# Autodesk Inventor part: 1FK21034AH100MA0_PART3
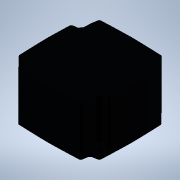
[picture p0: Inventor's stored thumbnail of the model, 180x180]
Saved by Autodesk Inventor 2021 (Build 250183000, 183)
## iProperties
Created: 2025-04
Part Number: 1FK21034AH100MA0_PART3
Material: Generic
Catalog Web Link: www.3dfindit.com
Description: -Servo synchronous motor
Document SubType Name: Modeling
Designer: psAdmin
Mass: 116.584 g
Surface Area: 147.122 cm^2
Volume: 116.584 cm^3
Density: 1 g/cm^3
Appearance: PSOLRGB-38-46-56
Category: PARTsolutions
Title: 1FK21034AH100MA0_PART3
Author: Cadenas PARTsolutions
Comments: Servo synchronous motor
Sending System: PARTsolutions
Preprocessor: ST-DEVELOPER v19.3
PSOL_IDENT_0: {$CADENAS_DATA/23d-libs/siemens_ag/_cat_/39/97/1fk21034ah100ma0.prj},213 {VTYP=3D},{NB=1FK21034AH100
PSOL_IDENT_1: MA0_PART3},{LINA=1FK21034AH100MA0_PART3},{NN=1FK21034AH100MA0_PART3},{NOPRJ=TRUE},{DATE=19.08.2025 1
PSOL_IDENT_2: 4:00:33},{GEOMDATE=30.07.2025 02:02:21},{VERSION=},{LINEID=10},{WBVAR=},{WBNUMERIC=}  {NB=1FK21034AH
PSOL_IDENT_3: 100MA0_PART3},{LINA=1FK21034AH100MA0_PART3},{KT=DUMMY},{PREVIEW=../../../_pool_/d3/78/p_d211_xx_0093
PSOL_IDENT_4: 4j.png},{DESCSHORT=SIMOTICS S-1FK2 HD, SINAMICS S210 3AC 400V-480V, 1.01 Nm, 4500 rpm},{DESCLONG=SIM
PSOL_IDENT_5: OTICS S-1FK2 HD servo motor M0=1.27 Nm; PN = 0.48 kW at nN=4500 rpm (380-480 V); PN = 0.3 kW at nN=2
PSOL_IDENT_6: 500 rpm (200-240 V); with holding brake; degree of protection IP64; cylindrical shaft D14 x 30 mm; a
PSOL_IDENT_7: bsolute encoder 22-bit + 12-bit multiturn (encoder AM22DQC); with OCC interface; plug size M17, rota
PSOL_IDENT_8: table; SIMOTICS S-1FK2 servomotorfor a wide range of uses in industrial environments. SIMOTICS S‑1FK
PSOL_IDENT_9: 2 servomotors are compact synchronous motors with a high dynamic performance that set themselves apa
PSOL_IDENT_10: rt as a result of their high power density, degree of protection and overload capability. The motors
PSOL_IDENT_11: are available in two variants: as High Dynamic variant (highest dynamic performance as a result of
PSOL_IDENT_12: the low intrinsic moment of inertia for applications demanding a high dynamic performance with low m
PSOL_IDENT_13: oved masses) - and as Compact variant (precise and stable closed-loop control for medium up to large
PSOL_IDENT_14: moved masses as a result of a medium intrinsic moment of inertia). SIMOTICSS‑1FK2 servomotors fully
PSOL_IDENT_15: exploit their strengths in a system with the SINAMICSS210 frequency converter and simple connection
PSOL_IDENT_16: using the one cable connection (OCC). Advantages include the short control and positioning times, f
PSOL_IDENT_17: ast and precise correction of disturbing quantities as well as stable control with a high dynamic pe
PSOL_IDENT_18: rformance. The servo motors can be configured to address a wide range of requirements. For example w
PSOL_IDENT_19: ith and without holding brake, IP64 or IP65 degree of protection, singleturn or multiturn absolute e
PSOL_IDENT_20: ncoders - to name just a few. Further, the servomotors are available in different shaft heights exte
PSOL_IDENT_21: nding from 20 to 100. A shaft sealing ring is available to achieve an IP65 degree of protection and
PSOL_IDENT_22: for subsequent mounting at the motor or as spare part. SIMOTICS - the optimum motor for each and eve
PSOL_IDENT_23: ry motion control application.},{INTNO=195125454019},{SUPPLIERALTNO=1FK2103-4AH10-0MA0},{MANUID=1FK2
PSOL_IDENT_24: 1034AH100MA0},{MANUNAME=Siemens},{MANUTYPEDESC=SYNCHRONOUS MOTOR 1FK2 HD 1,27 NM},{AAU732=SIMOTICS},
PSOL_IDENT_25: {AAO057=S-1FK2},{AAU734=SIMOTICS S-1FK2 HD servo motor M0=1.27 Nm; PN = 0.48 kW at nN=4500 rpm (380-
PSOL_IDENT_26: 480 V); PN = 0.3 kW at nN=2500 rpm (200-240 V); with holding brake; degree of protection IP64; cylin
PSOL_IDENT_27: drical shaft D14 x 30 mm; absolute encoder 22-bit + 12-bit multiturn (encoder AM22DQC); with OCC int
PSOL_IDENT_28: erface; plug size M17, rotatable;},{AAW338=SYNCHRONOUS MOTOR 1FK2 HD 1,27 NM},{AAO742=SIMOTICS},{AAO
PSOL_IDENT_29: 663=4034106444921},{NOCUPEROU=1},{PRICEQUANTITY=1},{QUANTITYMIN=1},{QUANTITYINT=1},{CTN=85015100},{C
PSOL_IDENT_30: OO=RO},{AAO676=1FK2103-4AH10-0MA0},{AAO677=Siemens AG},{ORDERUNIT=C62},{CONTENTUNIT=C62}
NB: 1FK21034AH100MA0_PART3
NT: Servo synchronous motor
NBSYN: $MANUID._PART3
LINA: 1FK21034AH100MA0_PART3
CATALOG: SIEMENS
PREVIEW: ../../../_pool_/d3/78/p_d211_xx_00934j.png
DESCSHORT: SIMOTICS S-1FK2 HD, SINAMICS S210 3AC 400V-480V, 1.01 Nm, 4500 rpm
DESCLONG: SIMOTICS S-1FK2 HD servo motor M0=1.27 Nm; PN = 0.48 kW at nN=4500 rpm (380-480 V); PN = 0.3 kW at nN=2500 rpm (200-240 V); with holding brake; degree of protec
INTNO: 195125454019
SUPPLIERALTNO: 1FK2103-4AH10-0MA0
MANUID: 1FK21034AH100MA0
MANUNAME: Siemens
MANUTYPEDESC: SYNCHRONOUS MOTOR 1FK2 HD 1,27 NM
AAU732: SIMOTICS
AAO057: S-1FK2
AAU734: SIMOTICS S-1FK2 HD servo motor M0=1.27 Nm; PN = 0.48 kW at nN=4500 rpm (380-480 V); PN = 0.3 kW at nN=2500 rpm (200-240 V); with holding brake; degree of protec
AAW338: SYNCHRONOUS MOTOR 1FK2 HD 1,27 NM
AAO742: SIMOTICS
AAO663: 4034106444921.0
NOCUPEROU: 1
PRICEQUANTITY: 1
QUANTITYMIN: 1
QUANTITYINT: 1
CTN: 85015100
COO: RO
ARTICLENO: 1FK21034AH100MA0_PART3
BOMINFO: 1FK21034AH100MA0_PART3
CREATOR: CADENAS GmbH
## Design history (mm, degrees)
feature "2025_04_17_15_09_00_0236"
body "Solid1"
